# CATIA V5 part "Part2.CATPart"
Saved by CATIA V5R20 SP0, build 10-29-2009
Part number: Part2
Bounding box of the stored display mesh (mm): x -270 to 60, y -60 to 60, z -20 to 350
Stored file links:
  E:\Ehsan\Amoozesh\CATIA\CATIA Course\Advanced\Exercises\DMU Kinematic\5\Part2.CATPart
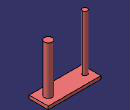
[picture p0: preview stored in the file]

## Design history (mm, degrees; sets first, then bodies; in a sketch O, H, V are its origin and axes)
Body1 (main body)
  DatumSurface1
  Sketch1 on face of DatumSurface1, origin (0, 0, 0), H (1, 0, 0), V (0, 1, 0)
    line L1 (-270, 60) -> (60, 60)
    line L2 (60, 60) -> (60, -60)
    line L3 (60, -60) -> (-270, -60)
    line L4 (-270, -60) -> (-270, 60)
    horizontal: L1 H, L3 H
    vertical: L2 V, L4 V
  Pad1: profile Sketch1, direction (0, 0, -1), length 20
  DatumCurve1
  Sketch2 on end face of Pad1, origin (0, 0, -20), H (1, 0, 0), V (0, -1, 0)
    circle A1 centre (0, 0) radius 25
  Pad2: profile Sketch2, direction (0, 0, 1), length 320
  Sketch3 on start face of Pad1, origin (0, 0, 0), H (1, 0, 0), V (0, 1, 0)
    circle A1 centre (-230, 0) radius 15
    point P1 (-230, 0)
    radius A1 = 15
    coincidence: P1 H
  Pad3: profile Sketch3, direction (0, 0, 1), length 350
